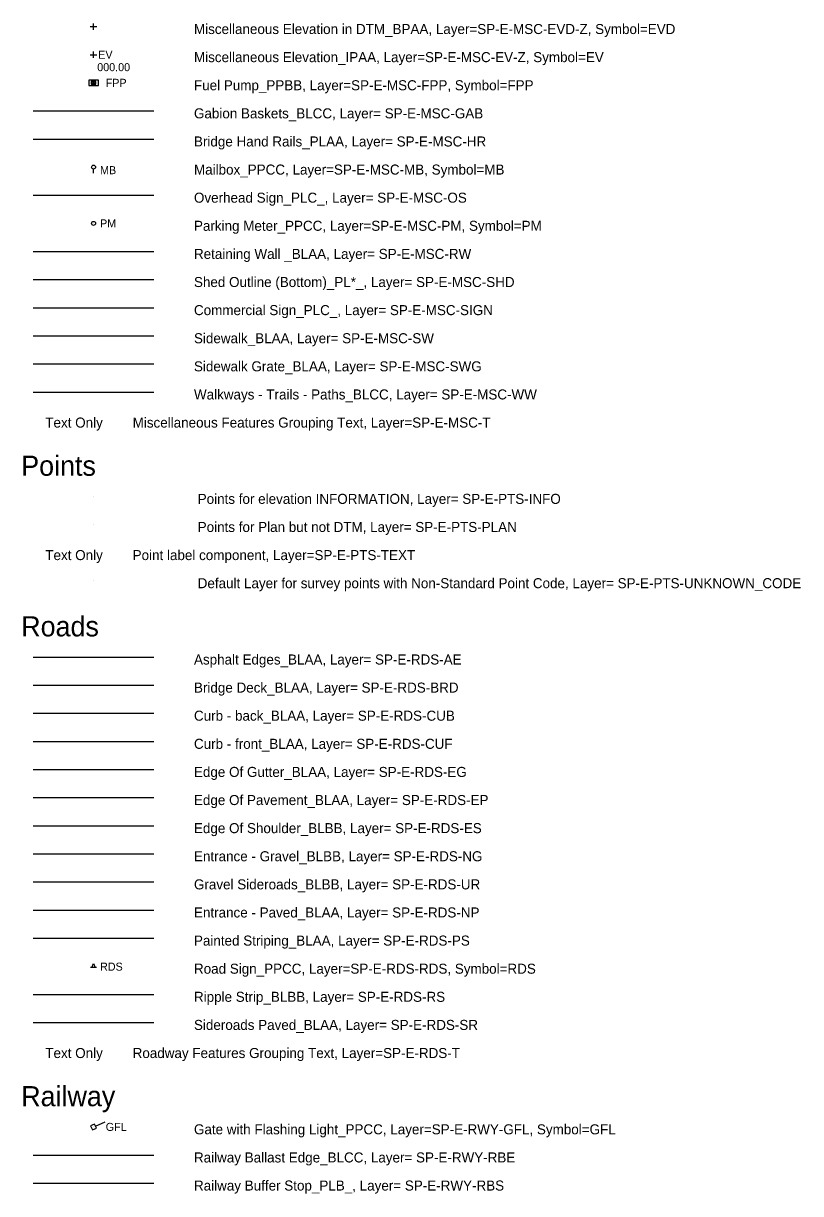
# Model space of a CAD drawing. Extents: x 500528 to 502626, y 4210261 to 4212624.
# Drawn here: x 501384.1 to 501577.5, y 4211442 to 4211733.4 of the extents above; entities that cross this region are included whole.
import ezdxf

# ---------------------------------------------------------------- set-up
doc = ezdxf.new("R2010")
doc.units = 0
for name, color, linetype in [('Default', 7, 'Continuous'), ('SP-E-MSC-EV-Z', 7, 'Continuous'), ('SP-E-MSC-EVD-Z', 7, 'Continuous'), ('SP-E-MSC-FPP', 7, 'Continuous'), ('SP-E-MSC-GAB', 7, 'Continuous'), ('SP-E-MSC-HR', 7, 'Continuous'), ('SP-E-MSC-MB', 7, 'Continuous'), ('SP-E-MSC-OS', 7, 'Continuous'), ('SP-E-MSC-PM', 7, 'Continuous'), ('SP-E-MSC-RW', 7, 'Continuous'), ('SP-E-MSC-SHD', 7, 'Continuous'), ('SP-E-MSC-SIGN', 7, 'Continuous'), ('SP-E-MSC-SW', 7, 'Continuous'), ('SP-E-MSC-SWG', 7, 'Continuous'), ('SP-E-MSC-T', 7, 'Continuous'), ('SP-E-MSC-WW', 7, 'Continuous'), ('SP-E-PTS-INFO', 7, 'Continuous'), ('SP-E-PTS-PLAN', 7, 'Continuous'), ('SP-E-PTS-TEXT', 7, 'Continuous'), ('SP-E-PTS-UNKNOWN_CODE', 7, 'Continuous'), ('SP-E-RDS-AE', 7, 'Continuous'), ('SP-E-RDS-BRD', 7, 'Continuous'), ('SP-E-RDS-CUB', 7, 'Continuous'), ('SP-E-RDS-CUF', 7, 'Continuous'), ('SP-E-RDS-EG', 7, 'Continuous'), ('SP-E-RDS-EP', 7, 'Continuous'), ('SP-E-RDS-ES', 7, 'Continuous'), ('SP-E-RDS-NG', 7, 'Continuous'), ('SP-E-RDS-NP', 7, 'Continuous'), ('SP-E-RDS-PS', 7, 'Continuous'), ('SP-E-RDS-RDS', 7, 'Continuous'), ('SP-E-RDS-RS', 7, 'Continuous'), ('SP-E-RDS-SR', 7, 'Continuous'), ('SP-E-RDS-T', 7, 'Continuous'), ('SP-E-RDS-UR', 7, 'Continuous'), ('SP-E-RWY-GFL', 7, 'Continuous'), ('SP-E-RWY-RBE', 7, 'Continuous'), ('SP-E-RWY-RBS', 7, 'Continuous'), ('SP-E-RWY-T', 7, 'Continuous')]:
    doc.layers.add(name, color=color, linetype=linetype)

# ---------------------------------------------------------------- blocks, each defined once
blk = doc.blocks.new('POINT_DISPLAY')
at = {"layer": 'Default'}
blk.add_line((0, 0), (0, 0), dxfattribs=at)
blk = doc.blocks.new('EVD')
at = {"layer": 'SP-E-MSC-T'}
for points in [[(-0.08, 0), (0.08, 0)], [(0, -0.08), (0, 0.08)]]:
    blk.add_lwpolyline(points, dxfattribs=at)
at = {"layer": 'SP-E-MSC-EVD-Z'}
blk.add_blockref('POINT_DISPLAY', (0, 0), dxfattribs=at)
blk = doc.blocks.new('EV')
at = {"layer": 'SP-E-MSC-EV-Z'}
for points in [[(-0.08, 0), (0.08, 0)], [(0, -0.08), (0, 0.08)]]:
    blk.add_lwpolyline(points, dxfattribs=at)
at = {"layer": 'SP-E-MSC-T'}
for s, p in [('EV', (0.117, -0.1)), ('000.00', (0.092, -0.41))]:
    blk.add_text(s, height=0.2, dxfattribs=at).set_placement(p)
blk = doc.blocks.new('FPP')
at = {"layer": 'SP-E-MSC-FPP'}
for points in [[(-0.12, -0.065), (0.12, -0.065), (0.12, 0.065), (-0.12, 0.065), (-0.12, -0.065)], [(-0.059, -0.032), (0.059, -0.032), (0.059, 0.032), (-0.059, 0.032), (-0.059, -0.032)], [(0.059, 0.032), (-0.059, -0.032)], [(-0.059, 0.032), (0.059, -0.032)]]:
    blk.add_lwpolyline(points, dxfattribs=at)
at = {"layer": 'SP-E-MSC-T'}
blk.add_text('FPP', height=0.2, dxfattribs=at).set_placement((0.303, -0.1))
blk = doc.blocks.new('MB')
at = {"layer": 'SP-E-MSC-MB'}
for points in [[(0, 0), (0, 0)], [(0, -0.15), (0, -0.05)]]:
    blk.add_lwpolyline(points, dxfattribs=at)
blk.add_circle((0, 0), 0.0495, dxfattribs=at)
at = {"layer": 'SP-E-MSC-T'}
blk.add_text('MB', height=0.2, dxfattribs=at).set_placement((0.162, -0.175))
blk = doc.blocks.new('PM')
at = {"layer": 'SP-E-MSC-PM'}
blk.add_lwpolyline([(0, 0), (0, 0)], dxfattribs=at)
blk.add_circle((0, 0), 0.05, dxfattribs=at)
at = {"layer": 'SP-E-MSC-T'}
blk.add_text('PM', height=0.2, dxfattribs=at).set_placement((0.162, -0.1))
blk = doc.blocks.new('RDS')
at = {"layer": 'SP-E-RDS-RDS'}
for points in [[(-0.041, -0.033), (0, 0.066), (0.041, -0.033)], [(0.075, -0.033), (-0.075, -0.033)]]:
    blk.add_lwpolyline(points, dxfattribs=at)
at = {"layer": 'SP-E-RDS-T'}
blk.add_text('RDS', height=0.2, dxfattribs=at).set_placement((0.162, -0.109))
blk = doc.blocks.new('GFL')
at = {"layer": 'SP-E-RWY-GFL'}
for points in [[(0.028, 0.072), (-0.072, 0.028)], [(0.028, 0.072), (-0.072, 0.028)], [(-0.072, 0.028), (-0.028, -0.072)], [(-0.072, 0.028), (-0.028, -0.072)], [(0, 0), (0, 0)], [(0.072, -0.028), (0.028, 0.072)], [(0.05, 0.022), (0.028, 0.072)], [(0.05, 0.022), (0.292, 0.128)], [(0.072, -0.028), (0.05, 0.022)], [(-0.028, -0.072), (0.072, -0.028)], [(-0.028, -0.072), (0.072, -0.028)]]:
    blk.add_lwpolyline(points, dxfattribs=at)
at = {"layer": 'SP-E-RWY-T'}
blk.add_text('GFL', height=0.2, dxfattribs=at).set_placement((0.303, -0.1))

msp = doc.modelspace()

# ---------------------------------------------------------------- linework, layer by layer
at = {"layer": 'SP-E-MSC-GAB'}
msp.add_line((501386.55, 4211711.59), (501416.55, 4211711.59), dxfattribs=at)
at = {"layer": 'SP-E-MSC-HR'}
msp.add_line((501386.55, 4211704.59), (501416.55, 4211704.59), dxfattribs=at)
at = {"layer": 'SP-E-MSC-OS'}
msp.add_line((501386.55, 4211690.59), (501416.55, 4211690.59), dxfattribs=at)
at = {"layer": 'SP-E-MSC-RW'}
msp.add_line((501386.55, 4211676.59), (501416.55, 4211676.59), dxfattribs=at)
at = {"layer": 'SP-E-MSC-SHD'}
msp.add_line((501386.55, 4211669.59), (501416.55, 4211669.59), dxfattribs=at)
at = {"layer": 'SP-E-MSC-SIGN'}
msp.add_line((501386.55, 4211662.59), (501416.55, 4211662.59), dxfattribs=at)
at = {"layer": 'SP-E-MSC-SW'}
msp.add_line((501386.55, 4211655.59), (501416.55, 4211655.59), dxfattribs=at)
at = {"layer": 'SP-E-MSC-SWG'}
msp.add_line((501386.55, 4211648.59), (501416.55, 4211648.59), dxfattribs=at)
at = {"layer": 'SP-E-MSC-WW'}
msp.add_line((501386.55, 4211641.59), (501416.55, 4211641.59), dxfattribs=at)
at = {"layer": 'SP-E-RDS-AE'}
msp.add_line((501386.55, 4211575.59), (501416.55, 4211575.59), dxfattribs=at)
at = {"layer": 'SP-E-RDS-BRD'}
msp.add_line((501386.55, 4211568.59), (501416.55, 4211568.59), dxfattribs=at)
at = {"layer": 'SP-E-RDS-CUB'}
msp.add_line((501386.55, 4211561.59), (501416.55, 4211561.59), dxfattribs=at)
at = {"layer": 'SP-E-RDS-CUF'}
msp.add_line((501386.55, 4211554.59), (501416.55, 4211554.59), dxfattribs=at)
at = {"layer": 'SP-E-RDS-EG'}
msp.add_line((501386.55, 4211547.59), (501416.55, 4211547.59), dxfattribs=at)
at = {"layer": 'SP-E-RDS-EP'}
msp.add_line((501386.55, 4211540.59), (501416.55, 4211540.59), dxfattribs=at)
at = {"layer": 'SP-E-RDS-ES'}
msp.add_line((501386.55, 4211533.59), (501416.55, 4211533.59), dxfattribs=at)
at = {"layer": 'SP-E-RDS-NG'}
msp.add_line((501386.55, 4211526.59), (501416.55, 4211526.59), dxfattribs=at)
at = {"layer": 'SP-E-RDS-NP'}
msp.add_line((501386.55, 4211512.59), (501416.55, 4211512.59), dxfattribs=at)
at = {"layer": 'SP-E-RDS-PS'}
msp.add_line((501386.55, 4211505.59), (501416.55, 4211505.59), dxfattribs=at)
at = {"layer": 'SP-E-RDS-RS'}
msp.add_line((501386.55, 4211491.59), (501416.55, 4211491.59), dxfattribs=at)
at = {"layer": 'SP-E-RDS-SR'}
msp.add_line((501386.55, 4211484.59), (501416.55, 4211484.59), dxfattribs=at)
at = {"layer": 'SP-E-RDS-UR'}
msp.add_line((501386.55, 4211519.59), (501416.55, 4211519.59), dxfattribs=at)
at = {"layer": 'SP-E-RWY-RBE'}
msp.add_line((501386.55, 4211451.59), (501416.55, 4211451.59), dxfattribs=at)
at = {"layer": 'SP-E-RWY-RBS'}
msp.add_line((501386.55, 4211444.59), (501416.55, 4211444.59), dxfattribs=at)

# ---------------------------------------------------------------- block references
at = {"layer": 'SP-E-MSC-EV-Z', "xscale": 10, "yscale": 10}
msp.add_blockref('EV', (501401.55, 4211725.59), dxfattribs=at)
at = {"layer": 'SP-E-MSC-EVD-Z', "xscale": 10, "yscale": 10}
msp.add_blockref('EVD', (501401.55, 4211732.59), dxfattribs=at)
at = {"layer": 'SP-E-MSC-FPP', "xscale": 10, "yscale": 10}
msp.add_blockref('FPP', (501401.55, 4211718.59), dxfattribs=at)
at = {"layer": 'SP-E-MSC-MB', "xscale": 10, "yscale": 10}
msp.add_blockref('MB', (501401.55, 4211697.59), dxfattribs=at)
at = {"layer": 'SP-E-MSC-PM', "xscale": 10, "yscale": 10}
msp.add_blockref('PM', (501401.55, 4211683.59), dxfattribs=at)
at = {"layer": 'SP-E-PTS-INFO', "xscale": 10, "yscale": 10}
msp.add_blockref('POINT_DISPLAY', (501401.55, 4211615.59), dxfattribs=at)
at = {"layer": 'SP-E-PTS-PLAN', "xscale": 10, "yscale": 10}
msp.add_blockref('POINT_DISPLAY', (501401.55, 4211608.59), dxfattribs=at)
at = {"layer": 'SP-E-PTS-UNKNOWN_CODE', "xscale": 10, "yscale": 10}
msp.add_blockref('POINT_DISPLAY', (501401.55, 4211594.59), dxfattribs=at)
at = {"layer": 'SP-E-RDS-RDS', "xscale": 10, "yscale": 10}
msp.add_blockref('RDS', (501401.55, 4211498.59), dxfattribs=at)
at = {"layer": 'SP-E-RWY-GFL', "xscale": 10, "yscale": 10}
msp.add_blockref('GFL', (501401.55, 4211458.59), dxfattribs=at)

# ---------------------------------------------------------------- texts
at = {"layer": 'Default'}
for s, p in [('Points ', (501383.55, 4211620.74)), ('Roads ', (501383.55, 4211580.74)), ('Railway ', (501383.55, 4211463.74))]:
    msp.add_text(s, height=5, dxfattribs=at).set_placement(p)
at = {"layer": 'SP-E-MSC-EV-Z'}
msp.add_text('Miscellaneous Elevation_IPAA, Layer=SP-E-MSC-EV-Z, Symbol=EV ', height=2.5, dxfattribs=at).set_placement((501426.55, 4211723.74))
at = {"layer": 'SP-E-MSC-EVD-Z'}
msp.add_text('Miscellaneous Elevation in DTM_BPAA, Layer=SP-E-MSC-EVD-Z, Symbol=EVD ', height=2.5, dxfattribs=at).set_placement((501426.55, 4211730.74))
at = {"layer": 'SP-E-MSC-FPP'}
msp.add_text('Fuel Pump_PPBB, Layer=SP-E-MSC-FPP, Symbol=FPP ', height=2.5, dxfattribs=at).set_placement((501426.55, 4211716.74))
at = {"layer": 'SP-E-MSC-GAB'}
msp.add_text('Gabion Baskets_BLCC, Layer= SP-E-MSC-GAB ', height=2.5, dxfattribs=at).set_placement((501426.55, 4211709.74))
at = {"layer": 'SP-E-MSC-HR'}
msp.add_text('Bridge Hand Rails_PLAA, Layer= SP-E-MSC-HR ', height=2.5, dxfattribs=at).set_placement((501426.55, 4211702.74))
at = {"layer": 'SP-E-MSC-MB'}
msp.add_text('Mailbox_PPCC, Layer=SP-E-MSC-MB, Symbol=MB ', height=2.5, dxfattribs=at).set_placement((501426.55, 4211695.74))
at = {"layer": 'SP-E-MSC-OS'}
msp.add_text('Overhead Sign_PLC_, Layer= SP-E-MSC-OS ', height=2.5, dxfattribs=at).set_placement((501426.55, 4211688.74))
at = {"layer": 'SP-E-MSC-PM'}
msp.add_text('Parking Meter_PPCC, Layer=SP-E-MSC-PM, Symbol=PM ', height=2.5, dxfattribs=at).set_placement((501426.55, 4211681.74))
at = {"layer": 'SP-E-MSC-RW'}
msp.add_text('Retaining Wall _BLAA, Layer= SP-E-MSC-RW ', height=2.5, dxfattribs=at).set_placement((501426.55, 4211674.74))
at = {"layer": 'SP-E-MSC-SHD'}
msp.add_text('Shed Outline (Bottom)_PL*_, Layer= SP-E-MSC-SHD ', height=2.5, dxfattribs=at).set_placement((501426.55, 4211667.74))
at = {"layer": 'SP-E-MSC-SIGN'}
msp.add_text('Commercial Sign_PLC_, Layer= SP-E-MSC-SIGN ', height=2.5, dxfattribs=at).set_placement((501426.55, 4211660.74))
at = {"layer": 'SP-E-MSC-SW'}
msp.add_text('Sidewalk_BLAA, Layer= SP-E-MSC-SW ', height=2.5, dxfattribs=at).set_placement((501426.55, 4211653.74))
at = {"layer": 'SP-E-MSC-SWG'}
msp.add_text('Sidewalk Grate_BLAA, Layer= SP-E-MSC-SWG ', height=2.5, dxfattribs=at).set_placement((501426.55, 4211646.74))
at = {"layer": 'SP-E-MSC-T'}
msp.add_text('Text Only        Miscellaneous Features Grouping Text, Layer=SP-E-MSC-T', height=2.5, dxfattribs=at).set_placement((501389.55, 4211632.74))
at = {"layer": 'SP-E-MSC-WW'}
msp.add_text('Walkways - Trails - Paths_BLCC, Layer= SP-E-MSC-WW ', height=2.5, dxfattribs=at).set_placement((501426.55, 4211639.74))
at = {"layer": 'SP-E-PTS-INFO'}
msp.add_text(' Points for elevation INFORMATION, Layer= SP-E-PTS-INFO ', height=2.5, dxfattribs=at).set_placement((501426.55, 4211613.74))
at = {"layer": 'SP-E-PTS-PLAN'}
msp.add_text(' Points for Plan but not DTM, Layer= SP-E-PTS-PLAN ', height=2.5, dxfattribs=at).set_placement((501426.55, 4211606.74))
at = {"layer": 'SP-E-PTS-TEXT'}
msp.add_text('Text Only        Point label component, Layer=SP-E-PTS-TEXT', height=2.5, dxfattribs=at).set_placement((501389.55, 4211599.74))
at = {"layer": 'SP-E-PTS-UNKNOWN_CODE'}
msp.add_text(' Default Layer for survey points with Non-Standard Point Code, Layer= SP-E-PTS-UNKNOWN_CODE ', height=2.5, dxfattribs=at).set_placement((501426.55, 4211592.74))
at = {"layer": 'SP-E-RDS-AE'}
msp.add_text('Asphalt Edges_BLAA, Layer= SP-E-RDS-AE ', height=2.5, dxfattribs=at).set_placement((501426.55, 4211573.74))
at = {"layer": 'SP-E-RDS-BRD'}
msp.add_text('Bridge Deck_BLAA, Layer= SP-E-RDS-BRD ', height=2.5, dxfattribs=at).set_placement((501426.55, 4211566.74))
at = {"layer": 'SP-E-RDS-CUB'}
msp.add_text('Curb - back_BLAA, Layer= SP-E-RDS-CUB ', height=2.5, dxfattribs=at).set_placement((501426.55, 4211559.74))
at = {"layer": 'SP-E-RDS-CUF'}
msp.add_text('Curb - front_BLAA, Layer= SP-E-RDS-CUF ', height=2.5, dxfattribs=at).set_placement((501426.55, 4211552.74))
at = {"layer": 'SP-E-RDS-EG'}
msp.add_text('Edge Of Gutter_BLAA, Layer= SP-E-RDS-EG ', height=2.5, dxfattribs=at).set_placement((501426.55, 4211545.74))
at = {"layer": 'SP-E-RDS-EP'}
msp.add_text('Edge Of Pavement_BLAA, Layer= SP-E-RDS-EP ', height=2.5, dxfattribs=at).set_placement((501426.55, 4211538.74))
at = {"layer": 'SP-E-RDS-ES'}
msp.add_text('Edge Of Shoulder_BLBB, Layer= SP-E-RDS-ES ', height=2.5, dxfattribs=at).set_placement((501426.55, 4211531.74))
at = {"layer": 'SP-E-RDS-NG'}
msp.add_text('Entrance - Gravel_BLBB, Layer= SP-E-RDS-NG ', height=2.5, dxfattribs=at).set_placement((501426.55, 4211524.74))
at = {"layer": 'SP-E-RDS-NP'}
msp.add_text('Entrance - Paved_BLAA, Layer= SP-E-RDS-NP ', height=2.5, dxfattribs=at).set_placement((501426.55, 4211510.74))
at = {"layer": 'SP-E-RDS-PS'}
msp.add_text('Painted Striping_BLAA, Layer= SP-E-RDS-PS ', height=2.5, dxfattribs=at).set_placement((501426.55, 4211503.74))
at = {"layer": 'SP-E-RDS-RDS'}
msp.add_text('Road Sign_PPCC, Layer=SP-E-RDS-RDS, Symbol=RDS ', height=2.5, dxfattribs=at).set_placement((501426.55, 4211496.74))
at = {"layer": 'SP-E-RDS-RS'}
msp.add_text('Ripple Strip_BLBB, Layer= SP-E-RDS-RS ', height=2.5, dxfattribs=at).set_placement((501426.55, 4211489.74))
at = {"layer": 'SP-E-RDS-SR'}
msp.add_text('Sideroads Paved_BLAA, Layer= SP-E-RDS-SR ', height=2.5, dxfattribs=at).set_placement((501426.55, 4211482.74))
at = {"layer": 'SP-E-RDS-T'}
msp.add_text('Text Only        Roadway Features Grouping Text, Layer=SP-E-RDS-T', height=2.5, dxfattribs=at).set_placement((501389.55, 4211475.74))
at = {"layer": 'SP-E-RDS-UR'}
msp.add_text('Gravel Sideroads_BLBB, Layer= SP-E-RDS-UR ', height=2.5, dxfattribs=at).set_placement((501426.55, 4211517.74))
at = {"layer": 'SP-E-RWY-GFL'}
msp.add_text('Gate with Flashing Light_PPCC, Layer=SP-E-RWY-GFL, Symbol=GFL ', height=2.5, dxfattribs=at).set_placement((501426.55, 4211456.74))
at = {"layer": 'SP-E-RWY-RBE'}
msp.add_text('Railway Ballast Edge_BLCC, Layer= SP-E-RWY-RBE ', height=2.5, dxfattribs=at).set_placement((501426.55, 4211449.74))
at = {"layer": 'SP-E-RWY-RBS'}
msp.add_text('Railway Buffer Stop_PLB_, Layer= SP-E-RWY-RBS ', height=2.5, dxfattribs=at).set_placement((501426.55, 4211442.74))

doc.saveas('drawing.dxf')
